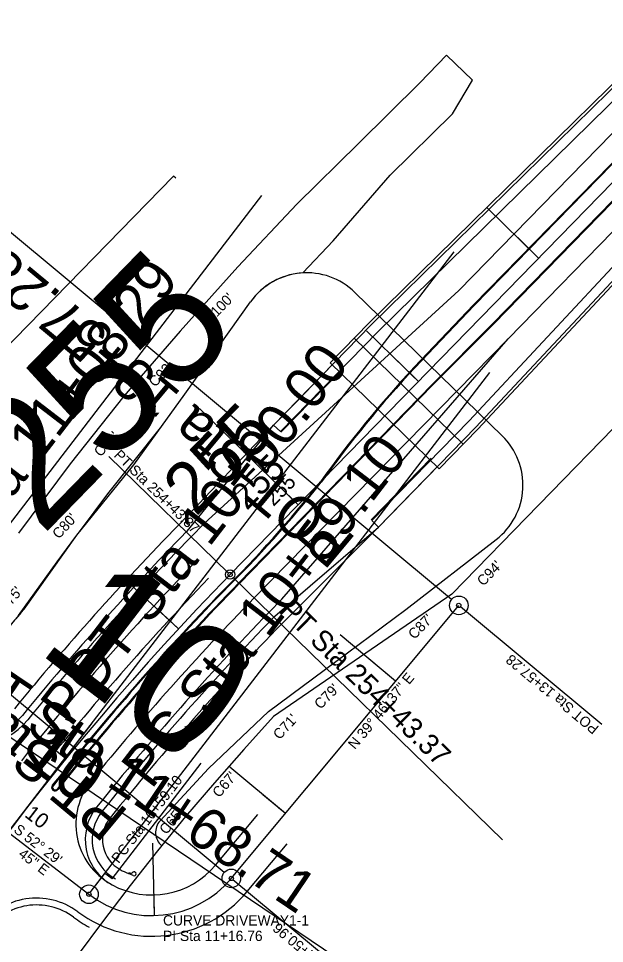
# Model space of a CAD drawing. Extents: x 2358865 to 2362945, y 393485 to 404880.
# Drawn here: x 2359566 to 2359906, y 397834 to 398371 of the extents above; entities that cross this region are included whole.
import ezdxf

# ---------------------------------------------------------------- set-up
doc = ezdxf.new("R2010")
doc.units = 0
for name, color, linetype in [('CL', 7, 'Continuous'), ('Level 11', 7, 'Continuous'), ('Level 12', 7, 'Continuous'), ('Level 19', 7, 'Continuous'), ('Level 21', 7, 'Continuous'), ('Level 22', 7, 'Continuous'), ('Level 25', 7, 'Continuous'), ('Level 27', 7, 'Continuous'), ('Level 28', 7, 'Continuous'), ('Level 30', 7, 'Continuous'), ('Level 33', 7, 'Continuous'), ('Level 35', 7, 'Continuous'), ('Level 36', 7, 'Continuous'), ('Level 37', 7, 'Continuous'), ('Level 39', 7, 'Continuous'), ('Level 40', 7, 'Continuous'), ('Level 41', 7, 'Continuous'), ('Level 48', 7, 'Continuous'), ('Level 50', 7, 'Continuous'), ('Level 51', 7, 'Continuous'), ('Level 52', 7, 'Continuous'), ('Level 53', 7, 'Continuous'), ('Level 58', 7, 'Continuous'), ('Level 61', 7, 'Continuous'), ('PTS-MISC', 7, 'Continuous'), ('STAEQU', 7, 'Continuous')]:
    doc.layers.add(name, color=color, linetype=linetype)

msp = doc.modelspace()

# ---------------------------------------------------------------- linework, layer by layer
at = {"layer": 'CL'}
for p, q in [((2359688.9, 398047.82), (2361589.92, 399999.4)), ((2359689.63, 397871.36), (2359821.63, 398029.92)), ((2359560.1, 397898.13), (2359606.99, 397862.15))]:
    msp.add_line(p, q, dxfattribs=at)
for centre, radius, start, end in [((2360835.02, 396931.39), 1600, 135.75191, 198.12413), ((2359643.51, 397909.75), 60, 232.4958, 320.223)]:
    msp.add_arc(centre, radius, start, end, dxfattribs=at)
at = {"layer": 'Level 11'}
for p, q in [((2359663.98, 398073.11), (2359714.15, 398134.65)), ((2359714.84, 398023.57), (2359775.04, 398075.34)), ((2359663.48, 398072.6), (2359663.98, 398073.11)), ((2359714.34, 398023.05), (2359714.84, 398023.57))]:
    msp.add_line(p, q, dxfattribs=at)
for centre, radius, start, end in [((2360835.02, 396931.39), 1635.5, 135.75153, 140.75675), ((2360835.02, 396931.39), 1564.5, 135.75152, 141.26921), ((2359540.5, 397988.81), 36, 232.4958, 320.7568), ((2359634.85, 397893.97), 26, 141.2692, 241.2193), ((2359576.6, 397819.94), 36, 53.3123, 144.775), ((2359643.51, 397909.75), 76, 233.3123, 241.4468)]:
    msp.add_arc(centre, radius, start, end, dxfattribs=at)
at = {"layer": 'Level 12'}
for p, q in [((2359748.21, 398169.61), (2359726.4, 398147.23)), ((2359714.15, 398134.65), (2359726.4, 398147.23)), ((2359659.69, 398077.3), (2359714.15, 398134.65)), ((2359787.29, 398087.92), (2359809.1, 398110.3)), ((2359775.04, 398075.34), (2359787.29, 398087.92)), ((2359659.18, 398076.78), (2359659.69, 398077.3)), ((2359719.14, 398019.38), (2359775.04, 398075.34)), ((2359632.71, 397872.96), (2359629.88, 397874.28))]:
    msp.add_line(p, q, dxfattribs=at)
for centre, radius, start, end in [((2360835.02, 396931.39), 1641.5, 135.75153, 140.75675), ((2360835.02, 396931.39), 1558.5, 135.72454, 141.26921), ((2359634.85, 397893.97), 20, 141.2692, 241.2193), ((2359643.51, 397909.75), 38, 241.2193, 248.9683), ((2359633.19, 397874), 1.15, 245.0857, 65.0879)]:
    msp.add_arc(centre, radius, start, end, dxfattribs=at)
msp.add_spline([(2359633.68, 397875.04), (2359633.45, 397875.15), (2359632.57, 397875.03), (2359632.31, 397874.7), (2359631.56, 397874.3), (2359630.95, 397874.36), (2359630.38, 397874.43), (2359629.88, 397874.28)], degree=3, dxfattribs=at)
at = {"layer": 'Level 19'}
for p, q in [((2359821.6, 398212.71), (2361205.32, 399633.23)), ((2359850.25, 398184.8), (2361233.97, 399605.32)), ((2359673.81, 398077.47), (2359821.6, 398212.71)), ((2359718.94, 398033.51), (2359850.25, 398184.8)), ((2359666.35, 398069.81), (2359673.81, 398077.47)), ((2359711.48, 398025.85), (2359718.94, 398033.51)), ((2359680.4, 397879.04), (2359704.92, 397908.48)), ((2359698.85, 397863.68), (2359722, 397891.5))]:
    msp.add_line(p, q, dxfattribs=at)
for centre, radius, start, end in [((2360835.02, 396931.39), 1631.5, 135.75153, 140.75675), ((2360835.02, 396931.39), 1568.5, 135.75152, 141.26921), ((2359540.5, 397988.81), 40, 232.4958, 320.7568), ((2359634.85, 397893.97), 30, 141.2692, 241.2193), ((2359643.51, 397909.75), 48, 241.2193, 320.223), ((2359643.51, 397909.75), 72, 233.3123, 320.223), ((2359576.6, 397819.94), 40, 53.3123, 144.775)]:
    msp.add_arc(centre, radius, start, end, dxfattribs=at)
at = {"layer": 'Level 25'}
for p, q in [((2359867.97, 398231.64), (2359864.39, 398235.13)), ((2359798.19, 398160.01), (2359794.61, 398163.5)), ((2359728.41, 398088.38), (2359722.68, 398093.96)), ((2359659.06, 398016.34), (2359655.39, 398019.73)), ((2359784.98, 397985.9), (2359781.14, 397989.1)), ((2359593.59, 397940.77), (2359589.71, 397943.93)), ((2359721, 397909.05), (2359717.16, 397912.25)), ((2359645.14, 397849.77), (2359645.01, 397854.77))]:
    msp.add_line(p, q, dxfattribs=at)
at = {"layer": 'Level 27'}
for p, q in [((2359817.49, 398036.51), (2361439.8, 399701.97)), ((2359556.38, 398176.9), (2359656.09, 398279.26)), ((2359657.51, 398277.92), (2359656.09, 398279.26)), ((2359817.49, 398036.51), (2359714.19, 397965.48))]:
    msp.add_line(p, q, dxfattribs=at)
msp.add_arc((2360835.02, 396931.39), 1525, 137.30515, 198.12413, dxfattribs=at)
at = {"layer": 'Level 28'}
for p, q in [((2359618.53, 398116.37), (2359688.01, 398048.69)), ((2359904.67, 397960.79), (2359822.59, 398029.12)), ((2359620.53, 397871.02), (2359672.19, 397938.33)), ((2359607.75, 397863.14), (2359616.29, 397874.27)), ((2359620.53, 397871.02), (2359616.29, 397874.27)), ((2359764.64, 397808.92), (2359690.59, 397870.56))]:
    msp.add_line(p, q, dxfattribs=at)
for centre in [(2359688.9, 398047.82), (2359821.63, 398029.92), (2359689.63, 397871.36), (2359606.99, 397862.15)]:
    msp.add_circle(centre, 1.25, dxfattribs=at)
at = {"layer": 'Level 30'}
for p, q in [((2359867.97, 398231.64), (2359861.88, 398237.58)), ((2359798.19, 398160.01), (2359792.1, 398165.94)), ((2359728.41, 398088.38), (2359716.95, 398099.54)), ((2359659.06, 398016.34), (2359652.82, 398022.1)), ((2359593.59, 397940.77), (2359587, 397946.14))]:
    msp.add_line(p, q, dxfattribs=at)
at = {"layer": 'Level 33'}
msp.add_line((2359690.84, 398045.93), (2359847.05, 397893.77), dxfattribs=at)
msp.add_circle((2359688.9, 398047.82), 2.7, dxfattribs=at)
at = {"layer": 'Level 35'}
for p, q in [((2359821.6, 398212.71), (2361205.32, 399633.23)), ((2359850.25, 398184.8), (2361233.97, 399605.32)), ((2359673.81, 398077.47), (2359821.6, 398212.71)), ((2359702.88, 398034.22), (2359850.25, 398184.8))]:
    msp.add_line(p, q, dxfattribs=at)
for centre, radius, start, end in [((2360835.02, 396931.39), 1580.5, 135.75152, 140.9043), ((2359639.45, 397902.86), 40, 140.9043, 240.8014)]:
    msp.add_arc(centre, radius, start, end, dxfattribs=at)
at = {"layer": 'Level 36'}
for radius in [1619.5, 1607.5]:
    msp.add_arc((2360835.53, 396931.91), radius, 136.14456, 141.51611, dxfattribs=at)
at = {"layer": 'Level 37'}
for p, q in [((2359830.24, 398204.38), (2361213.91, 399624.85)), ((2359830.6, 398204.03), (2361214.27, 399624.51)), ((2359841.34, 398193.56), (2361225.02, 399614.04)), ((2359841.7, 398193.21), (2361225.37, 399613.69)), ((2359830.24, 398204.38), (2359795.71, 398168.21)), ((2359830.6, 398204.03), (2359796.07, 398167.86)), ((2359841.34, 398193.56), (2359806.09, 398158.09)), ((2359841.7, 398193.21), (2359806.45, 398157.74)), ((2359693.92, 398042.93), (2359806.09, 398158.09)), ((2359694.28, 398042.58), (2359806.45, 398157.74))]:
    msp.add_line(p, q, dxfattribs=at)
for centre, radius, start, end in [((2360286.45, 397712.07), 670, 137.09265, 144.43739), ((2360286.45, 397712.07), 669.5, 137.09265, 144.43739), ((2359215.05, 398516.26), 670, 314.45805, 321.77898), ((2359215.05, 398516.26), 670.5, 314.45805, 321.77898), ((2360835.02, 396931.39), 1593, 135.75191, 141.48989), ((2360835.02, 396931.39), 1592.5, 135.75191, 141.48989), ((2360835.02, 396931.39), 1596.5, 136.11841, 141.48989), ((2360835.02, 396931.39), 1596, 136.11841, 141.48989), ((2359587.33, 397924.21), 2, 141.5161, 321.5161), ((2359587.33, 397924.21), 1.5, 141.5161, 321.5161)]:
    msp.add_arc(centre, radius, start, end, dxfattribs=at)
at = {"layer": 'Level 39'}
for p, q in [((2359867.97, 398231.64), (2359855.79, 398243.51)), ((2359798.19, 398160.01), (2359786.01, 398171.87)), ((2359728.41, 398088.38), (2359705.49, 398110.71)), ((2359659.06, 398016.34), (2359646.57, 398027.87)), ((2359784.98, 397985.9), (2359771.92, 397996.78)), ((2359593.59, 397940.77), (2359580.4, 397951.5)), ((2359560.1, 397898.13), (2359579.59, 397923.52)), ((2359721, 397909.05), (2359707.94, 397919.92)), ((2359645.14, 397849.77), (2359644.68, 397866.76))]:
    msp.add_line(p, q, dxfattribs=at)
at = {"layer": 'Level 40'}
for p, q in [((2359817.48, 398033.38), (2359493, 398303.51)), ((2359477.49, 397968.34), (2359707.35, 398267.86)), ((2359563.39, 397902.41), (2359818.86, 398235.29)), ((2359610.27, 397866.43), (2359839.56, 398165.21)), ((2359685.48, 397874.82), (2359393.13, 398118.19)), ((2359469.89, 398015.16), (2359772.13, 397810.89))]:
    msp.add_line(p, q, dxfattribs=at)
for centre in [(2359821.63, 398029.92), (2359689.63, 397871.36), (2359606.99, 397862.15)]:
    msp.add_circle(centre, 5.4, dxfattribs=at)
at = {"layer": 'Level 41'}
for p, q in [((2359867.97, 398231.64), (2359837.88, 398260.95)), ((2359798.19, 398160.01), (2359768.11, 398189.32)), ((2359728.41, 398088.38), (2359671.11, 398144.2)), ((2359659.06, 398016.34), (2359628.19, 398044.82)), ((2359784.98, 397985.9), (2359752.7, 398012.77)), ((2359593.59, 397940.77), (2359561.01, 397967.27)), ((2359560.1, 397898.13), (2359608.81, 397961.59)), ((2359721, 397909.05), (2359688.72, 397935.92)), ((2359645.14, 397849.77), (2359644, 397891.76))]:
    msp.add_line(p, q, dxfattribs=at)
at = {"layer": 'Level 48'}
for p, q in [((2361214.27, 399624.51), (2359830.6, 398204.03)), ((2359841.34, 398193.56), (2361225.02, 399614.04)), ((2359830.6, 398204.03), (2359796.07, 398167.87)), ((2359806.09, 398158.09), (2359841.34, 398193.56)), ((2359693.93, 398042.94), (2359806.09, 398158.09))]:
    msp.add_line(p, q, dxfattribs=at)
for centre, radius, start, end in [((2360286.45, 397712.07), 669.5, 137.09279, 144.43838), ((2359215.05, 398516.26), 670.5, 314.45867, 321.77997), ((2360835.02, 396931.39), 1593, 135.75153, 141.48989), ((2360835.02, 396931.39), 1596, 136.11867, 141.48989), ((2359587.33, 397924.21), 1.5, 141.5161, 321.5161)]:
    msp.add_arc(centre, radius, start, end, dxfattribs=at)
at = {"layer": 'Level 50'}
for p, q in [((2359662.56, 398152.53), (2359700.85, 398206.27)), ((2359633.01, 398111.51), (2359662.56, 398152.53)), ((2359600.03, 398070.76), (2359633.01, 398111.51)), ((2359569.43, 398027.81), (2359600.03, 398070.76)), ((2359790.84, 398027.57), (2359843.34, 398068.17)), ((2359750.2, 397997.36), (2359790.84, 398027.57)), ((2359711.27, 397968.22), (2359750.2, 397997.36)), ((2359676.43, 397935.19), (2359711.27, 397968.22)), ((2359648.3, 397904.82), (2359676.43, 397935.19))]:
    msp.add_line(p, q, dxfattribs=at)
for centre, radius, start, end in [((2360834.47, 396930.74), 1674.49, 139.0676, 140.61661), ((2359655.64, 397898.03), 10, 137.1918, 230.318)]:
    msp.add_arc(centre, radius, start, end, dxfattribs=at)
at = {"layer": 'Level 51'}
msp.add_line((2359761.33, 398211.7), (2359846.78, 398128.47), dxfattribs=at)
at = {"layer": 'Level 52'}
for centre, start, end in [((2359733.42, 398183.05), 45.7519, 144.5258), ((2359818.87, 398099.82), 307.7165, 45.7519)]:
    msp.add_arc(centre, 40, start, end, dxfattribs=at)
at = {"layer": 'Level 58'}
for p, q in [((2359769.47, 398193.77), (2359947.85, 398369.01)), ((2359832.69, 398132.19), (2360003.19, 398315.11)), ((2359747.05, 398170.74), (2359769.47, 398193.77)), ((2359761, 398185.07), (2359824.22, 398123.49)), ((2359810.26, 398109.17), (2359747.05, 398170.74)), ((2359810.26, 398109.17), (2359832.69, 398132.19))]:
    msp.add_line(p, q, dxfattribs=at)
at = {"layer": 'Level 61'}
for p, q in [((2359814.42, 398349.42), (2359799.11, 398333.44)), ((2359829.58, 398334.89), (2359814.42, 398349.42)), ((2359799.11, 398333.44), (2359763.48, 398298.16)), ((2359817.88, 398315.46), (2359829.58, 398334.89)), ((2359781.77, 398279.69), (2359817.88, 398315.46)), ((2359763.48, 398298.16), (2359727.72, 398262.96)), ((2359748.76, 398241.58), (2359781.77, 398279.69)), ((2359727.72, 398262.96), (2359693.33, 398226.56)), ((2359731.21, 398222.99), (2359748.76, 398241.58)), ((2359693.33, 398226.56), (2359660, 398189.25)), ((2359662.56, 398152.53), (2359700.85, 398206.27)), ((2359660, 398189.25), (2359627.27, 398151.41)), ((2359627.27, 398151.41), (2359596.04, 398112.17)), ((2359649.11, 398133.86), (2359662.56, 398152.53)), ((2359617.95, 398094.74), (2359648.44, 398133.09)), ((2359648.44, 398133.09), (2359649.11, 398133.86)), ((2359596.04, 398112.17), (2359566.13, 398071.88)), ((2359601.62, 398072.72), (2359617.95, 398094.74)), ((2359596.79, 398066.21), (2359600.03, 398070.76)), ((2359600.03, 398070.76), (2359601.62, 398072.72)), ((2359588.61, 398055.19), (2359596.79, 398066.21)), ((2359566.14, 398024.01), (2359588.61, 398055.19))]:
    msp.add_line(p, q, dxfattribs=at)
for centre, radius, start, end in [((2359733.42, 398183.05), 40, 93.1707, 144.5258), ((2360834.47, 396930.74), 1674.49, 139.23944, 140.61661)]:
    msp.add_arc(centre, radius, start, end, dxfattribs=at)
at = {"layer": 'PTS-MISC'}
for p, q in [((2359718.45, 398130.46), (2359753.34, 398166.28)), ((2359770.74, 398079.52), (2359805.63, 398115.34))]:
    msp.add_line(p, q, dxfattribs=at)
at = {"layer": 'STAEQU'}
for p, q in [((2359770.64, 398192.63), (2359949.02, 398367.88)), ((2359952.96, 398364.04), (2359774.58, 398188.8)), ((2359827.58, 398137.16), (2359998.09, 398320.08)), ((2360002.03, 398316.24), (2359831.52, 398133.32)), ((2359714.15, 398134.65), (2359770.64, 398192.63)), ((2359774.58, 398188.8), (2359718.09, 398130.81)), ((2359718.09, 398130.81), (2359714.15, 398134.65)), ((2359771.1, 398079.17), (2359827.58, 398137.16)), ((2359831.52, 398133.32), (2359775.04, 398075.34)), ((2359775.04, 398075.34), (2359771.1, 398079.17))]:
    msp.add_line(p, q, dxfattribs=at)

# ---------------------------------------------------------------- texts
at = {"layer": 'Level 21'}
for s, rotation, p in [('N 39%%d 46\' 37" E', 50.223, (2359761.39, 397945.84)), ("S 52%%d 29'", 322.4958, (2359562.85, 397898.65)), ('45" E', 322.4958, (2359565.62, 397884.55))]:
    msp.add_text(s, height=6, rotation=rotation, dxfattribs=at).set_placement(p)
at = {"layer": 'Level 22'}
for s, p in [('CURVE DRIVEWAY1-1', (2359650, 397844)), ('CURVE DRIVEWAY1-1', (2359650, 397844)), ('PI Sta 11+16.76', (2359650, 397835)), ('PI Sta 11+16.76', (2359650, 397835))]:
    msp.add_text(s, height=6, dxfattribs=at).set_placement(p)
at = {"layer": 'Level 25'}
for s, rotation, p in [('255', 45.7519, (2359714.17, 398087.01)), ('10', 322.4958, (2359569.14, 397907.57))]:
    msp.add_text(s, height=8.75, rotation=rotation, dxfattribs=at).set_placement(p)
at = {"layer": 'Level 28'}
for s, rotation, p in [('PT Sta 254+43.37', 315.7519, (2359621.08, 398116.63)), ('POT Sta 13+57.28', 140.223, (2359903.39, 397959.26)), ('PC Sta 10+59.10', 52.4958, (2359624.29, 397879.66)), ('PT Sta 11+50.96', 140.223, (2359763.36, 397807.38))]:
    msp.add_text(s, height=6, rotation=rotation, dxfattribs=at).set_placement(p)
at = {"layer": 'Level 30'}
msp.add_text('255', height=15, rotation=45.7519, dxfattribs=at).set_placement((2359698.69, 398084.67))
at = {"layer": 'Level 33'}
msp.add_text('PT Sta 254+43.37', height=12, rotation=315.7519, dxfattribs=at).set_placement((2359716.77, 398026.26))
at = {"layer": 'Level 39'}
for s, rotation, p in [('255', 45.7519, (2359668.97, 398080.95)), ('10', 322.4958, (2359566.48, 397940.38))]:
    msp.add_text(s, height=30, rotation=rotation, dxfattribs=at).set_placement(p)
at = {"layer": 'Level 40'}
for s, rotation, p in [('POT Sta 13+57.28', 140.223, (2359762.71, 398068.56)), ('PC Sta 11+08.29', 52.4958, (2359510.47, 398024.46)), ('POT Sta 10+00.00', 52.4958, (2359596.37, 397958.53)), ('PC Sta 10+59.10', 52.4958, (2359643.26, 397922.55)), ('PT Sta 11+50.96', 140.223, (2359630.71, 397910)), ('PT Sta 11+68.71', 325.9468, (2359527.89, 397985.62))]:
    msp.add_text(s, height=24, rotation=rotation, dxfattribs=at).set_placement(p)
at = {"layer": 'Level 41'}
for s, rotation, p in [('255', 45.7519, (2359579.58, 398069.59)), ('10', 322.4958, (2359575.93, 398003.85))]:
    msp.add_text(s, height=75, rotation=rotation, dxfattribs=at).set_placement(p)
at = {"layer": 'Level 53'}
for s, rotation, p in [("C100'", 45.7519, (2359677.16, 398192.91)), ("C92'", 45.7519, (2359645.28, 398156.32)), ("C84'", 45.7519, (2359613.6, 398115.78)), ("C80'", 47.3052, (2359589.54, 398068.11)), ("C94'", 45.7519, (2359835.84, 398040.72)), ("C75'", 49.0957, (2359558.2, 398025.32)), ("C87'", 45.7519, (2359795.86, 398009.79)), ("C79'", 45.7519, (2359741.41, 397969.22)), ("C71'", 47.3052, (2359717.63, 397951.52)), ("C67'", 49.0957, (2359682.57, 397917.84)), ("C65'", 50.8862, (2359651.94, 397896.42))]:
    msp.add_text(s, height=6, rotation=rotation, dxfattribs=at).set_placement(p)

doc.saveas('drawing.dxf')
